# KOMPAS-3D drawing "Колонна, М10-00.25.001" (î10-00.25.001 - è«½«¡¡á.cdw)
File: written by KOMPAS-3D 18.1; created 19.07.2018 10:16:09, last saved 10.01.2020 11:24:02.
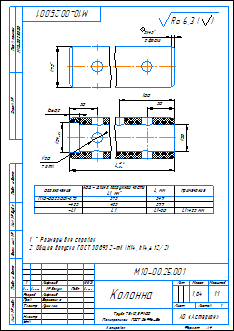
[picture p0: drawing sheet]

Sheet 1: A4, portrait

Document properties: Автор: Мирончук; Масса: 1.63515; Параметр неуказанной шероховатости: Ra 6,3; Полное имя файла: М10-00.25.001 - Колонна.m3d; Организация: Мирончук

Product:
- Part/product: Колонна  | designation М10-00.25.001
    Масса: 1.63515
    Раздел спецификации: Детали
    Форматы листов документа: A4
    source file: М10-00.25.001 - Колонна.cdw
- Part/product: Колонна ПВХ  | designation М13-01.25.001
    Масса: 0.762223
    Раздел спецификации: Детали
    Форматы листов документа: A4
    source file: ..\..\..\Магна ins 13\М13-01.00.000 ПВХ\Чертежи Компас\М13-01.25.001 - Колонна.cdw

Title block, sheet 1: Наименование: Колонна; designation: М10-00.25.001; Масса: 1,64; scale: 1:1; Количество листов документа: 1; organisation: АО «Астерион»; Форматы листов документа: A4; stored path: Z:\Магна\Магна Ins\Магна ins 10\М10-00.00.000\3Д\М10-00.25.001 - Колонна.cdw; Разработал: Лифлянд; Проверил: Борисенко; Т. контр.: Лучихин

Views: Вид 1, Сверху, Проекционный вид 2, Местный разрез 1
Referenced files in Z:\Магна\Магна Ins\Магна ins 10\М10-00.00.000\3Д\: М10-00.25.001 - Колонна.m3d
Referenced files in D:\Magna\Магна Ins\Магна ins 10\М10-00.00.000\3Д\: М10-00.25.001 - Колонна.m3d
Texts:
  КОД - Длина погружной части
  L1, мм*
  L, мм
  L1 425 мм
  Труба 75х12,5 PN20
  Полипропилен  ГОСТ 26996-86
  Ra 6,3
  Ra 6,3 ( )
Dimensions and other numbers on the sheet: 375; 349; -425; 425; 399; 5; 2 фаски; 75; 50; 100; 20; 7 отв.; 54; 18±0,2; 1; 1:1; 1,64; 10.01.20

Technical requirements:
  * Размеры для справок.
  Общие допуски ГОСТ 30893.2-mK (H14, h14,  t2/2).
